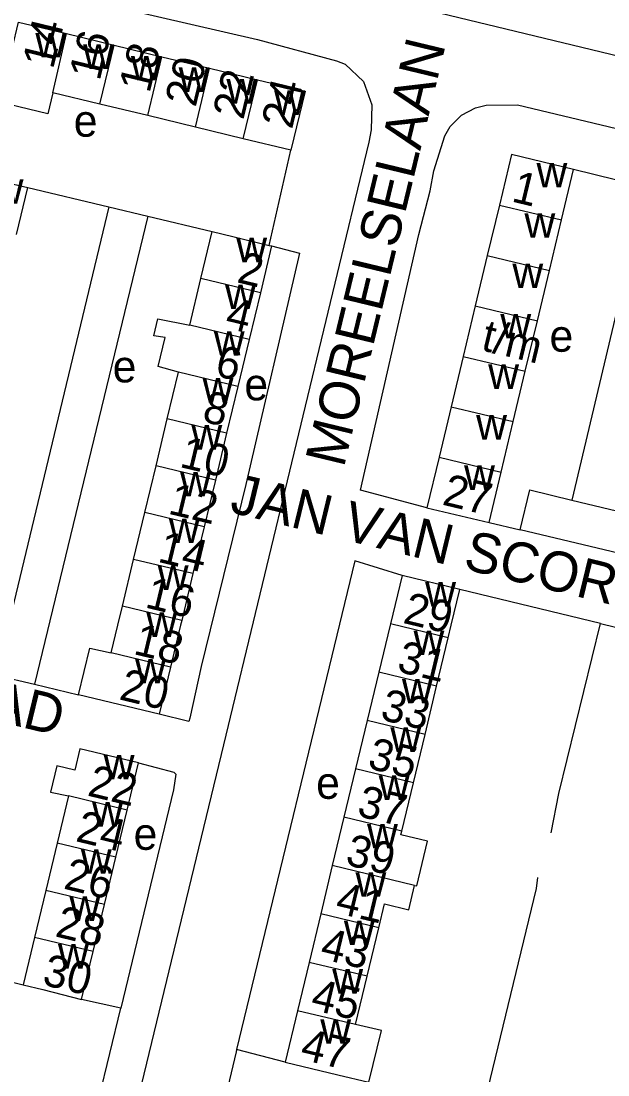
# Model space of a CAD drawing. Extents: x 162804 to 165059, y 381530 to 382901.
# Drawn here: x 163167.6 to 163241.1, y 382193.6 to 382325.7 of the extents above; entities that cross this region are included whole.
import ezdxf

# ---------------------------------------------------------------- set-up
doc = ezdxf.new("R2010")
doc.units = 0
for name, color, linetype in [('BLT_Basislijn', 7, 'Continuous'), ('BLT_Bebouwing', 7, 'Continuous'), ('BLT_Centroide', 7, 'Continuous'), ('BLT_Huisnummer', 7, 'Continuous'), ('BLT_Huisnummer_ tussenligend', 7, 'Continuous'), ('BLT_Huisnummer_reeks', 7, 'Continuous'), ('BLT_Onderverdeling_panden', 7, 'Continuous'), ('BLT_Straatnaam', 7, 'Continuous')]:
    doc.layers.add(name, color=color, linetype=linetype)

msp = doc.modelspace()

# ---------------------------------------------------------------- linework, layer by layer
at = {"layer": 'BLT_Basislijn'}
for p, q in [((163198.7, 382297.57), (163201.42, 382309.5)), ((163242.09, 382305.8), (163236.83, 382307.08)), ((163168.45, 382304.82), (163178.59, 382302.4)), ((163245.89, 382304.87), (163236.6, 382265.67)), ((163178.59, 382302.4), (163164.48, 382243.72)), ((163178.59, 382302.4), (163183.47, 382301.23)), ((163183.47, 382301.23), (163169.27, 382242.59)), ((163183.47, 382301.23), (163191.55, 382299.3)), ((163226.24, 382262.85), (163230.14, 382261.95)), ((163240.19, 382250.2), (163222.58, 382254.46)), ((163240.19, 382250.2), (163255.26, 382246.53)), ((163164.48, 382243.72), (163169.27, 382242.59)), ((163169.27, 382242.59), (163174.81, 382241.28)), ((163159.25, 382207.05), (163167.85, 382204.95)), ((163180.08, 382202), (163175.17, 382203.09)), ((163165.71, 382142.61), (163180.08, 382202)), ((163200.68, 382195.23), (163194.61, 382196.83))]:
    msp.add_line(p, q, dxfattribs=at)
for points in [[(163313.51, 382321.3), (163314.98, 382326.59), (163300, 382330.17), (163123.41, 382372.99), (163123.34, 382373.15), (163120.22, 382373.91), (163118.4, 382374.15), (163116.33, 382373.74), (163114.96, 382372.71), (163113.68, 382370.74), (163112.57, 382360.38), (163112.65, 382358.42), (163113.62, 382355.6), (163114.91, 382353.78), (163115.82, 382352.79), (163118.69, 382351.2), (163281.99, 382311.74), (163300, 382307.25), (163310, 382304.87), (163311.97, 382314.09)], [(163156.15, 382307.78), (163156.21, 382308.07), (163160.23, 382325.15), (163161.72, 382327.93), (163162.2, 382328.47), (163163.15, 382329.14), (163164.97, 382330), (163166.19, 382330.32), (163168.77, 382330.32), (163172.72, 382329.04), (163197.24, 382323.35), (163207.12, 382320.71), (163208.2, 382320.28), (163210.49, 382318.11), (163211.55, 382315.17), (163211.46, 382312.04), (163211.18, 382310.49), (163192.95, 382234.99)], [(163218.46, 382264.71), (163210.14, 382266.91), (163217.44, 382298.94), (163218.87, 382304.4), (163219.31, 382306.93), (163220.7, 382311.29), (163221.37, 382312.45), (163222.77, 382313.87), (163224.52, 382314.82), (163225.87, 382315.14), (163229.82, 382315.17), (163283.27, 382302.42), (163285.98, 382299.55), (163285.9, 382298.09), (163284.9, 382294.58), (163275.14, 382253.17), (163272.27, 382251.74), (163269.34, 382252.46)], [(163198.99, 382297.5), (163202.49, 382296.62), (163195.77, 382267.6), (163190.16, 382244.83), (163188.76, 382238.35), (163188.62, 382237.92), (163184.9, 382238.85)], [(163215.34, 382256.21), (163209.41, 382258.07), (163194.61, 382196.83)], [(163234.02, 382223.96), (163234.99, 382228.9), (163240.19, 382250.2)], [(163192.95, 382234.99), (163175.84, 382164.21), (163170.27, 382141.99), (163168.83, 382140.38), (163166.54, 382139.37), (163162.62, 382139.53), (163094.62, 382155.39), (163082.92, 382158.66), (163072.72, 382162.36)], [(163182.32, 382232.74), (163186.75, 382231.56), (163187, 382231.34), (163186.68, 382229.38), (163180.08, 382202)], [(163232.31, 382218.4), (163232.15, 382217.01), (163226.04, 382191.82)], [(163194.61, 382196.83), (163194.54, 382196.53), (163192.45, 382187.78)]]:
    msp.add_lwpolyline(points, dxfattribs=at)
at = {"layer": 'BLT_Bebouwing'}
for p, q in [((163173.28, 382324.1), (163179.26, 382322.66)), ((163179.26, 382322.66), (163185.25, 382321.21)), ((163185.25, 382321.21), (163191.23, 382319.77)), ((163191.23, 382319.77), (163197.22, 382318.32)), ((163177.48, 382315.28), (163171.59, 382316.7)), ((163183.47, 382313.83), (163177.48, 382315.28)), ((163189.45, 382312.39), (163183.47, 382313.83)), ((163195.44, 382310.94), (163189.45, 382312.39)), ((163201.42, 382309.5), (163195.44, 382310.94)), ((163235.32, 382300.76), (163236.83, 382307.08)), ((163167.04, 382298.95), (163168.45, 382304.82)), ((163227.54, 382302.62), (163226.02, 382296.3)), ((163233.8, 382294.44), (163235.32, 382300.76)), ((163190.14, 382293.43), (163191.55, 382299.3)), ((163198.99, 382297.5), (163197.58, 382291.64)), ((163198.7, 382297.57), (163198.99, 382297.5)), ((163226.02, 382296.3), (163224.51, 382289.99)), ((163188.74, 382287.56), (163190.14, 382293.43)), ((163232.29, 382288.12), (163233.8, 382294.44)), ((163197.58, 382291.64), (163196.18, 382285.77)), ((163224.51, 382289.99), (163223, 382283.67)), ((163230.78, 382281.81), (163232.29, 382288.12)), ((163196.18, 382285.77), (163194.77, 382279.91)), ((163223, 382283.67), (163221.49, 382277.35)), ((163185.92, 382275.83), (163187.33, 382281.7)), ((163229.27, 382275.49), (163230.78, 382281.81)), ((163194.77, 382279.91), (163193.36, 382274.04)), ((163221.49, 382277.35), (163219.98, 382271.04)), ((163184.51, 382269.97), (163185.92, 382275.83)), ((163227.76, 382269.17), (163229.27, 382275.49)), ((163193.36, 382274.04), (163191.96, 382268.18)), ((163219.98, 382271.04), (163218.46, 382264.71)), ((163183.11, 382264.1), (163184.51, 382269.97)), ((163226.24, 382262.85), (163227.76, 382269.17)), ((163191.96, 382268.18), (163190.55, 382262.31)), ((163236.6, 382265.67), (163244.48, 382263.77)), ((163218.46, 382264.71), (163226.24, 382262.85)), ((163181.7, 382258.23), (163183.11, 382264.1)), ((163190.55, 382262.31), (163189.14, 382256.45)), ((163243.28, 382258.79), (163230.14, 382261.95)), ((163180.29, 382252.37), (163181.7, 382258.23)), ((163189.14, 382256.45), (163187.73, 382250.58)), ((163215.34, 382256.21), (163213.87, 382250.16)), ((163222.58, 382254.46), (163215.34, 382256.21)), ((163219.67, 382242.36), (163221.13, 382248.41)), ((163186.32, 382244.72), (163184.9, 382238.85)), ((163212.42, 382244.1), (163210.96, 382238.04)), ((163218.22, 382236.3), (163219.67, 382242.36)), ((163184.9, 382238.85), (163174.81, 382241.28)), ((163210.96, 382238.04), (163209.51, 382231.98)), ((163216.77, 382230.24), (163218.22, 382236.3)), ((163180.9, 382226.83), (163182.32, 382232.74)), ((163209.51, 382231.98), (163208.05, 382225.92)), ((163215.31, 382224.18), (163216.77, 382230.24)), ((163173.56, 382228.6), (163172.13, 382222.69)), ((163179.47, 382220.92), (163180.9, 382226.83)), ((163208.05, 382225.92), (163206.6, 382219.87)), ((163172.13, 382222.69), (163170.71, 382216.77)), ((163178.04, 382215), (163179.47, 382220.92)), ((163206.6, 382219.87), (163205.14, 382213.81)), ((163170.71, 382216.77), (163169.28, 382210.86)), ((163176.62, 382209.09), (163178.04, 382215)), ((163205.14, 382213.81), (163203.69, 382207.75)), ((163210.95, 382206.01), (163212.41, 382212.06)), ((163169.28, 382210.86), (163167.85, 382204.95)), ((163175.17, 382203.09), (163176.62, 382209.09)), ((163203.69, 382207.75), (163202.23, 382201.69)), ((163209.5, 382199.95), (163210.95, 382206.01)), ((163202.23, 382201.69), (163200.68, 382195.23))]:
    msp.add_line(p, q, dxfattribs=at)
for points in [[(163164.87, 382315.51), (163167.29, 382325.55), (163173.28, 382324.1)], [(163197.22, 382318.32), (163203.2, 382316.88), (163201.42, 382309.5)], [(163171.59, 382316.7), (163170.95, 382314.04), (163164.87, 382315.51)], [(163236.83, 382307.08), (163229.05, 382308.94), (163227.54, 382302.62)], [(163162.51, 382306.25), (163165.95, 382305.42), (163168.45, 382304.82)], [(163191.55, 382299.3), (163194.13, 382298.67), (163198.7, 382297.57)], [(163187.33, 382281.7), (163184.79, 382282.38), (163185.67, 382286.02), (163184.23, 382286.26), (163184.74, 382288.39), (163188.74, 382287.56)], [(163230.14, 382261.95), (163231.34, 382266.93), (163236.6, 382265.67)], [(163221.13, 382248.41), (163221.51, 382250), (163222.58, 382254.46)], [(163178.88, 382246.51), (163179.73, 382250), (163180.29, 382252.37)], [(163187.73, 382250.58), (163187.59, 382250), (163186.32, 382244.72)], [(163213.87, 382250.16), (163213.83, 382250), (163212.42, 382244.1)], [(163174.81, 382241.28), (163176.21, 382247.13), (163178.88, 382246.51)], [(163182.32, 382232.74), (163174.98, 382234.51), (163174.34, 382231.82), (163172.07, 382232.37), (163171.27, 382229.06), (163173.56, 382228.6)], [(163216.91, 382217.39), (163217.17, 382217.33), (163218.51, 382222.92), (163215.2, 382223.71), (163215.31, 382224.18)], [(163212.41, 382212.06), (163213.13, 382215.08), (163216.17, 382214.35), (163216.91, 382217.39)], [(163167.85, 382204.95), (163170.33, 382204.35), (163175.17, 382203.09)], [(163211.18, 382192.74), (163212.76, 382199.2), (163209.5, 382199.95)], [(163200.68, 382195.23), (163207.27, 382193.67), (163211.18, 382192.74)]]:
    msp.add_lwpolyline(points, dxfattribs=at)
at = {"layer": 'BLT_Onderverdeling_panden'}
for p, q in [((163171.59, 382316.7), (163173.28, 382324.1)), ((163177.48, 382315.28), (163179.26, 382322.66)), ((163183.47, 382313.83), (163185.25, 382321.21)), ((163189.45, 382312.39), (163191.23, 382319.77)), ((163195.44, 382310.94), (163197.22, 382318.32)), ((163227.54, 382302.62), (163235.32, 382300.76)), ((163226.02, 382296.3), (163233.8, 382294.44)), ((163197.58, 382291.64), (163190.14, 382293.43)), ((163224.51, 382289.99), (163232.29, 382288.12)), ((163196.18, 382285.77), (163188.74, 382287.56)), ((163223, 382283.67), (163230.78, 382281.81)), ((163194.77, 382279.91), (163187.33, 382281.7)), ((163221.49, 382277.35), (163229.27, 382275.49)), ((163193.36, 382274.04), (163185.92, 382275.83)), ((163219.98, 382271.04), (163227.76, 382269.17)), ((163191.96, 382268.18), (163184.51, 382269.97)), ((163190.55, 382262.31), (163183.11, 382264.1)), ((163189.14, 382256.45), (163181.7, 382258.23)), ((163187.73, 382250.58), (163180.29, 382252.37)), ((163221.13, 382248.41), (163213.87, 382250.16)), ((163186.32, 382244.72), (163178.88, 382246.51)), ((163219.67, 382242.36), (163212.42, 382244.1)), ((163218.22, 382236.3), (163210.96, 382238.04)), ((163216.77, 382230.24), (163209.51, 382231.98)), ((163180.9, 382226.83), (163173.56, 382228.6)), ((163215.31, 382224.18), (163208.05, 382225.92)), ((163179.47, 382220.92), (163172.13, 382222.69)), ((163216.91, 382217.39), (163206.6, 382219.87)), ((163178.04, 382215), (163170.71, 382216.77)), ((163212.41, 382212.06), (163205.14, 382213.81)), ((163176.62, 382209.09), (163169.28, 382210.86)), ((163210.95, 382206.01), (163203.69, 382207.75)), ((163209.5, 382199.95), (163202.23, 382201.69))]:
    msp.add_line(p, q, dxfattribs=at)

# ---------------------------------------------------------------- texts
at = {"layer": 'BLT_Centroide'}
for s, p in [('w', (163169.39, 382321.12)), ('w', (163175.38, 382319.69)), ('w', (163181.36, 382318.25)), ('w', (163187.34, 382316.81)), ('w', (163193.33, 382315.34)), ('w', (163199.31, 382313.91)), ('e', (163174.2, 382311.19)), ('w', (163232.18, 382304.84)), ('w', (163164.04, 382302.78)), ('w', (163230.67, 382298.53)), ('w', (163194.56, 382295.47)), ('w', (163229.16, 382292.22)), ('w', (163193.16, 382289.59)), ('w', (163227.65, 382285.91)), ('w', (163191.75, 382283.75)), ('e', (163233.81, 382284.25)), ('e', (163179.08, 382280.41)), ('w', (163226.13, 382279.59)), ('w', (163190.34, 382277.88)), ('e', (163195.58, 382278.16)), ('w', (163224.62, 382273.25)), ('w', (163188.94, 382272)), ('w', (163223.11, 382266.94)), ('w', (163187.53, 382266.12)), ('w', (163186.12, 382260.28)), ('w', (163184.72, 382254.41)), ('w', (163218.23, 382252.31)), ('w', (163183.3, 382248.53)), ('w', (163216.77, 382246.25)), ('w', (163181.89, 382242.69)), ('w', (163215.32, 382240.19)), ('w', (163213.87, 382234.12)), ('w', (163177.95, 382230.66)), ('e', (163204.57, 382228.24)), ('w', (163212.41, 382228.09)), ('w', (163176.51, 382224.75)), ('e', (163181.7, 382221.85)), ('w', (163210.95, 382222.03)), ('w', (163175.09, 382218.84)), ('w', (163209.5, 382215.97)), ('w', (163173.66, 382212.94)), ('w', (163208.05, 382209.91)), ('w', (163172.23, 382206.97)), ('w', (163206.59, 382203.84)), ('w', (163205.09, 382197.56))]:
    msp.add_text(s, height=4, dxfattribs=at).set_placement(p)
at = {"layer": 'BLT_Huisnummer'}
for s, rotation, p in [('14', 76.4215, (163171.6, 382319.55)), ('18', 76.427, (163183.69, 382316.54)), ('24', 76.4232, (163201.54, 382312.03)), ('2', 346.4883, (163194.51, 382292.98)), ('6', 346.485, (163191.74, 382281.27)), ('10', 346.4891, (163187.33, 382269.84)), ('14', 346.4929, (163184.59, 382257.96)), ('29', 346.5034, (163215.32, 382250.3)), ('20', 346.5046, (163179.76, 382240.72)), ('33', 346.507, (163212.47, 382238.2)), ('22', 346.4405, (163175.78, 382228.67)), ('37', 346.5031, (163209.55, 382226.12)), ('26', 346.4387, (163172.8, 382217.01)), ('41', 346.5084, (163206.83, 382213.99)), ('30', 346.4392, (163170.11, 382204.98)), ('47', 346.6327, (163202.44, 382195.64))]:
    msp.add_text(s, height=4, rotation=rotation, dxfattribs=at).set_placement(p)
at = {"layer": 'BLT_Huisnummer_ tussenligend'}
for s, rotation, p in [('16', 76.4215, (163177.44, 382318.09)), ('20', 76.427, (163189.46, 382314.79)), ('22', 76.427, (163195.44, 382313.21)), ('4', 346.4883, (163193.03, 382287.27)), ('8', 346.485, (163190.15, 382275.55)), ('12', 346.4891, (163185.89, 382263.99)), ('16', 346.4929, (163183, 382252.24)), ('18', 346.4929, (163181.55, 382246.4)), ('31', 346.5034, (163214.56, 382244.22)), ('35', 346.507, (163210.88, 382232.09)), ('24', 346.4405, (163174.31, 382222.96)), ('39', 346.5031, (163208.1, 382220.01)), ('28', 346.4387, (163171.74, 382211.03)), ('43', 346.5084, (163204.93, 382208.25)), ('45', 346.5084, (163203.74, 382201.87))]:
    msp.add_text(s, height=4, rotation=rotation, dxfattribs=at).set_placement(p)
at = {"layer": 'BLT_Huisnummer_reeks'}
for s, rotation, p in [('1', 346.5371, (163228.92, 382303.1)), ('t/m', 346.5441, (163225.11, 382284.47)), ('27', 346.5371, (163220.24, 382265.12))]:
    msp.add_text(s, height=4, rotation=rotation, dxfattribs=at).set_placement(p)
at = {"layer": 'BLT_Straatnaam'}
for s, height, rotation, p in [('MOREELSELAAN', 5, 76.4507, (163208.03, 382269.62)), ('JAN VAN SCORELSTRAAT', 4.9999, 346.358, (163193.6, 382264.18)), ('DE BRAECKELEERPAD', 4.9999, 346.365, (163100.08, 382253.6))]:
    msp.add_text(s, height=height, rotation=rotation, dxfattribs=at).set_placement(p)

doc.saveas('drawing.dxf')
